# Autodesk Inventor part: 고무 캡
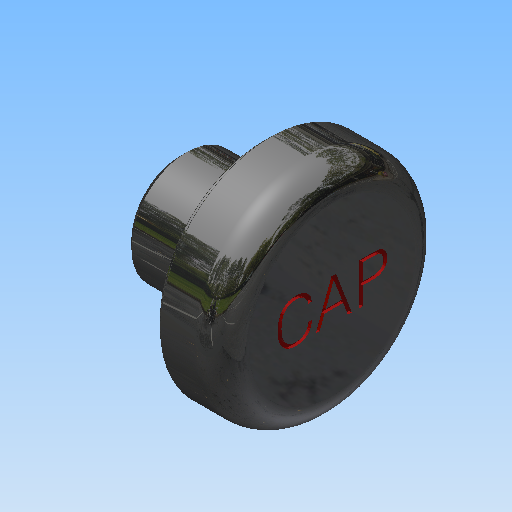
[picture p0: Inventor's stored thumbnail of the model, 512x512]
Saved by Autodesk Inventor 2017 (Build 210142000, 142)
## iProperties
Created: 2017-06
Part Number: 고무 캡
Material: 고무
Document SubType Name: Modeling
Designer: mduedu
Density: 1 g/cm^3
Appearance: 고무 - 검은색 - 버전 1.1
Author: mduedu
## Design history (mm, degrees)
sketch "스케치1"
  geometry: L1 (0, 0)-(11, 0); L2 (11, 0)-(11, 8); L3 (11, 8)-(6.5, 8); L4 (0, 4)-(0, 0); L5 (0, 4)-(6, 4); L6 (6, 4)-(6, 7.5); L7 (6, 7.5)-(6.5, 7.5); L8 (6.5, 7.5)-(6.5, 8)
  constraints: 16 end point, 2 horizontal, 2 parallel, 2 perpendicular, 2 point on line, 1 vertical
  dimensions: "d0" = 16 diameter of L3 L1; "d2" = 8 diameter of L5 L1; "d6" = 5 distance between parallel lines of L2 L6; "d7" = 0.5 distance between parallel lines of L8 L6; "d8" = 15 diameter of L7 L1; "d9" = 6 distance between parallel lines of L6 L4
revolve "회전1" sketch "스케치1" stored, may be unused: angle "d10" = 90 deg
hole "구멍1" diameter "d22" = 5; stored, may be unused: countersink angle "d26" = 90 deg, drill point angle "d28" = 0 deg; dims "d23" = 6, "d24" = 4, "d25" = 2, "d27" = 6, "d30" = 10, "d31" = 10
chamfer "모따기1" distance "d13" = 0.5; stored, may be unused: second distance "d14" = 2, angle "d15" = 45 deg
fillet "모깎기3" dims "d29" = 1
fillet "모깎기1" dims "d16" = 0.1
fillet "모깎기2" dims "d17" = 2
sketch "스케치3"
  geometry: 2 further points
  constraints: 1 coincident, 1 other
feature "엠보싱1" sketch "스케치3" dims "d18" = 0.2, "d19" = 0
node "솔리드1"
